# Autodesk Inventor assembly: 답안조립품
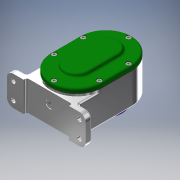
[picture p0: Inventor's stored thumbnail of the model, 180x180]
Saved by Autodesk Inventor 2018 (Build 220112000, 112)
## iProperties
Created: 2021-05
Part Number: 답안조립품
Material: 일반
Document SubType Name: Assembly
Designer: Admin
Author: Admin
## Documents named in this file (19)
- C:\Users\Admin\Desktop\710509V1002\답안조립품.iam
- C:\Users\Admin\Desktop\710509V1002\본체.ipt
- C:\Users\Admin\Desktop\710509V1002\축 A.ipt
- C:\Users\Admin\Desktop\710509V1002\베어링 6001.ipt
- 베어링 6001.ipt
- C:\Users\Admin\Desktop\710509V1002\베어링 6002.ipt
- 베어링 6002.ipt
- C:\Users\Admin\Desktop\710509V1002\칼라.ipt
- C:\Users\Admin\Desktop\710509V1002\키 5 x 5 x 12.ipt
- C:\Users\Admin\Desktop\710509V1002\스퍼기어 A.ipt
- C:\Users\Admin\Desktop\710509V1002\축 B.ipt
- C:\Users\Admin\Desktop\710509V1002\키 4 x 4 x 12.ipt
- C:\Users\Admin\Desktop\710509V1002\스퍼기어 B.ipt
- C:\Users\Admin\Desktop\710509V1002\개스킷 A.ipt
- C:\Users\Admin\Desktop\710509V1002\개스킷 B.ipt
- C:\Users\Admin\Desktop\710509V1002\커버 A.ipt
- C:\Users\Admin\Desktop\710509V1002\커버 B.ipt
- C:\Users\Admin\Desktop\710509V1002\볼트 M4.ipt
- C:\Users\Admin\Desktop\710509V1002\오일 실 12 22 7.ipt
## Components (2 placed, 2 different names)
1. 개스킷 A:1
2. 개스킷 B:1
